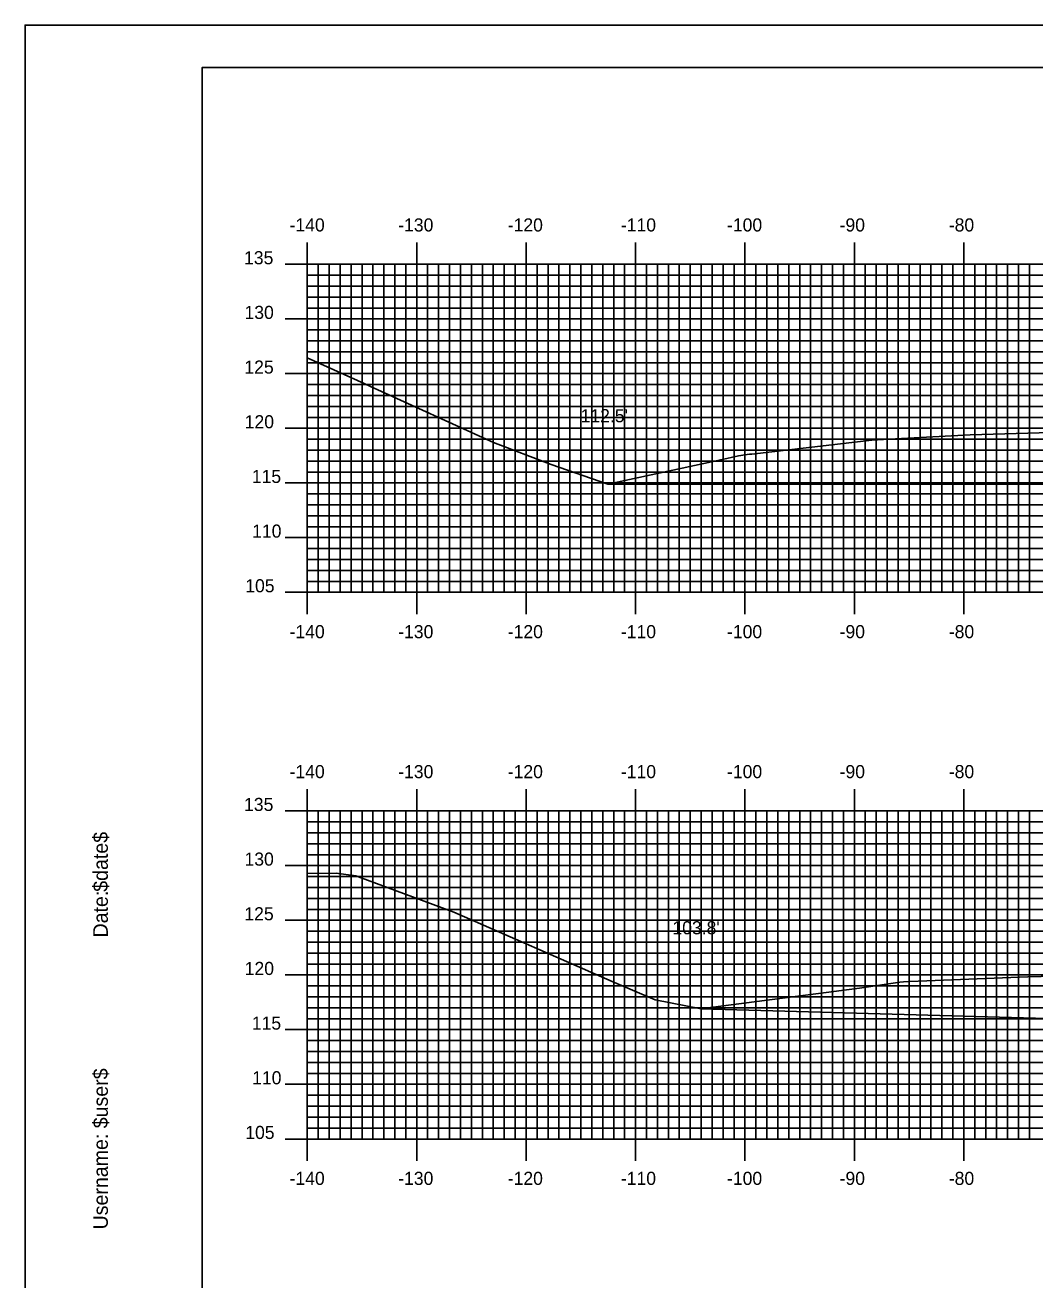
# Model space of a CAD drawing. Extents: x 854681 to 855024, y 366605 to 366825.
# Drawn here: x 854680.8 to 854773.1, y 366710.2 to 366824.9 of the extents above; entities that cross this region are included whole.
import ezdxf

# ---------------------------------------------------------------- set-up
doc = ezdxf.new("R2010")
doc.units = 0
for name, color, linetype in [('ANNOTATION', 7, 'Continuous'), ('BORDER', 7, 'Continuous'), ('D_Text_Standard', 7, 'Continuous'), ('H_V ANNOTATION', 7, 'Continuous'), ('MAJOR', 7, 'Continuous'), ('MINOR', 7, 'Continuous'), ('PLOT BOUNDARY', 7, 'Continuous'), ('S_Roadway_Centerline', 7, 'Continuous')]:
    doc.layers.add(name, color=color, linetype=linetype)

msp = doc.modelspace()

# ---------------------------------------------------------------- linework, layer by layer
at = {"layer": 'ANNOTATION'}
for points in [[(854804.38, 366783.93), (854800.38, 366782.93), (854734.03, 366782.96)], [(854804.38, 366734.36), (854800.38, 366733.36), (854742.57, 366734.98)]]:
    msp.add_lwpolyline(points, dxfattribs=at)
at = {"layer": 'BORDER'}
msp.add_lwpolyline([(854696.96, 366611.06), (855016.96, 366611.06), (855016.96, 366821.06), (854696.96, 366821.06)], close=True, dxfattribs=at)
at = {"layer": 'MAJOR'}
for p, q in [((854706.56, 366805.06), (854706.56, 366803.06)), ((854716.56, 366805.06), (854716.56, 366803.06)), ((854726.56, 366805.06), (854726.56, 366803.06)), ((854736.56, 366805.06), (854736.56, 366803.06)), ((854746.56, 366805.06), (854746.56, 366803.06)), ((854756.56, 366805.06), (854756.56, 366803.06)), ((854766.56, 366805.06), (854766.56, 366803.06)), ((854704.55, 366803.06), (854706.56, 366803.06)), ((854706.56, 366803.06), (854986.56, 366803.06)), ((854706.56, 366773.06), (854706.56, 366803.06)), ((854706.56, 366773.06), (854706.56, 366803.06)), ((854706.56, 366803.06), (854986.56, 366803.06)), ((854716.56, 366773.06), (854716.56, 366803.06)), ((854726.56, 366773.06), (854726.56, 366803.06)), ((854736.56, 366773.06), (854736.56, 366803.06)), ((854746.56, 366773.06), (854746.56, 366803.06)), ((854756.56, 366773.06), (854756.56, 366803.06)), ((854766.56, 366773.06), (854766.56, 366803.06)), ((854704.55, 366798.06), (854706.56, 366798.06)), ((854706.56, 366798.06), (854986.56, 366798.06)), ((854704.55, 366793.06), (854706.56, 366793.06)), ((854706.56, 366793.06), (854986.56, 366793.06)), ((854704.55, 366788.06), (854706.56, 366788.06)), ((854706.56, 366788.06), (854986.56, 366788.06)), ((854704.55, 366783.06), (854706.56, 366783.06)), ((854706.56, 366783.06), (854986.56, 366783.06)), ((854704.55, 366778.06), (854706.56, 366778.06)), ((854706.56, 366778.06), (854986.56, 366778.06)), ((854704.55, 366773.06), (854706.56, 366773.06)), ((854706.56, 366773.06), (854986.56, 366773.06)), ((854706.56, 366773.06), (854986.56, 366773.06)), ((854706.56, 366771.05), (854706.56, 366773.06)), ((854716.56, 366771.05), (854716.56, 366773.06)), ((854726.56, 366771.05), (854726.56, 366773.06)), ((854736.56, 366771.05), (854736.56, 366773.06)), ((854746.56, 366771.05), (854746.56, 366773.06)), ((854756.56, 366771.05), (854756.56, 366773.06)), ((854766.56, 366771.05), (854766.56, 366773.06)), ((854706.56, 366755.06), (854706.56, 366753.06)), ((854716.56, 366755.06), (854716.56, 366753.06)), ((854726.56, 366755.06), (854726.56, 366753.06)), ((854736.56, 366755.06), (854736.56, 366753.06)), ((854746.56, 366755.06), (854746.56, 366753.06)), ((854756.56, 366755.06), (854756.56, 366753.06)), ((854766.56, 366755.06), (854766.56, 366753.06)), ((854704.55, 366753.06), (854706.56, 366753.06)), ((854706.56, 366753.06), (854986.56, 366753.06)), ((854706.56, 366723.06), (854706.56, 366753.06)), ((854706.56, 366723.06), (854706.56, 366753.06)), ((854706.56, 366753.06), (854986.56, 366753.06)), ((854716.56, 366723.06), (854716.56, 366753.06)), ((854726.56, 366723.06), (854726.56, 366753.06)), ((854736.56, 366723.06), (854736.56, 366753.06)), ((854746.56, 366723.06), (854746.56, 366753.06)), ((854756.56, 366723.06), (854756.56, 366753.06)), ((854766.56, 366723.06), (854766.56, 366753.06)), ((854704.55, 366748.06), (854706.56, 366748.06)), ((854706.56, 366748.06), (854986.56, 366748.06)), ((854704.55, 366743.06), (854706.56, 366743.06)), ((854706.56, 366743.06), (854986.56, 366743.06)), ((854704.55, 366738.06), (854706.56, 366738.06)), ((854706.56, 366738.06), (854986.56, 366738.06)), ((854704.55, 366733.06), (854706.56, 366733.06)), ((854706.56, 366733.06), (854986.56, 366733.06)), ((854704.55, 366728.06), (854706.56, 366728.06)), ((854706.56, 366728.06), (854986.56, 366728.06)), ((854704.55, 366723.06), (854706.56, 366723.06)), ((854706.56, 366723.06), (854986.56, 366723.06)), ((854706.56, 366723.06), (854986.56, 366723.06)), ((854706.56, 366721.05), (854706.56, 366723.06)), ((854716.56, 366721.05), (854716.56, 366723.06)), ((854726.56, 366721.05), (854726.56, 366723.06)), ((854736.56, 366721.05), (854736.56, 366723.06)), ((854746.56, 366721.05), (854746.56, 366723.06)), ((854756.56, 366721.05), (854756.56, 366723.06)), ((854766.56, 366721.05), (854766.56, 366723.06))]:
    msp.add_line(p, q, dxfattribs=at)
at = {"layer": 'MINOR'}
for p, q in [((854707.56, 366773.06), (854707.56, 366803.06)), ((854708.56, 366773.06), (854708.56, 366803.06)), ((854709.56, 366773.06), (854709.56, 366803.06)), ((854710.56, 366773.06), (854710.56, 366803.06)), ((854711.56, 366773.06), (854711.56, 366803.06)), ((854712.56, 366773.06), (854712.56, 366803.06)), ((854713.56, 366773.06), (854713.56, 366803.06)), ((854714.56, 366773.06), (854714.56, 366803.06)), ((854715.56, 366773.06), (854715.56, 366803.06)), ((854717.56, 366773.06), (854717.56, 366803.06)), ((854718.56, 366773.06), (854718.56, 366803.06)), ((854719.56, 366773.06), (854719.56, 366803.06)), ((854720.56, 366773.06), (854720.56, 366803.06)), ((854721.56, 366773.06), (854721.56, 366803.06)), ((854722.56, 366773.06), (854722.56, 366803.06)), ((854723.56, 366773.06), (854723.56, 366803.06)), ((854724.56, 366773.06), (854724.56, 366803.06)), ((854725.56, 366773.06), (854725.56, 366803.06)), ((854727.56, 366773.06), (854727.56, 366803.06)), ((854728.56, 366773.06), (854728.56, 366803.06)), ((854729.56, 366773.06), (854729.56, 366803.06)), ((854730.56, 366773.06), (854730.56, 366803.06)), ((854731.56, 366773.06), (854731.56, 366803.06)), ((854732.56, 366773.06), (854732.56, 366803.06)), ((854733.56, 366773.06), (854733.56, 366803.06)), ((854734.56, 366773.06), (854734.56, 366803.06)), ((854735.56, 366773.06), (854735.56, 366803.06)), ((854737.56, 366773.06), (854737.56, 366803.06)), ((854738.56, 366773.06), (854738.56, 366803.06)), ((854739.56, 366773.06), (854739.56, 366803.06)), ((854740.56, 366773.06), (854740.56, 366803.06)), ((854741.56, 366773.06), (854741.56, 366803.06)), ((854742.56, 366773.06), (854742.56, 366803.06)), ((854743.56, 366773.06), (854743.56, 366803.06)), ((854744.56, 366773.06), (854744.56, 366803.06)), ((854745.56, 366773.06), (854745.56, 366803.06)), ((854747.56, 366773.06), (854747.56, 366803.06)), ((854748.56, 366773.06), (854748.56, 366803.06)), ((854749.56, 366773.06), (854749.56, 366803.06)), ((854750.56, 366773.06), (854750.56, 366803.06)), ((854751.56, 366773.06), (854751.56, 366803.06)), ((854752.56, 366773.06), (854752.56, 366803.06)), ((854753.56, 366773.06), (854753.56, 366803.06)), ((854754.56, 366773.06), (854754.56, 366803.06)), ((854755.56, 366773.06), (854755.56, 366803.06)), ((854757.56, 366773.06), (854757.56, 366803.06)), ((854758.56, 366773.06), (854758.56, 366803.06)), ((854759.56, 366773.06), (854759.56, 366803.06)), ((854760.56, 366773.06), (854760.56, 366803.06)), ((854761.56, 366773.06), (854761.56, 366803.06)), ((854762.56, 366773.06), (854762.56, 366803.06)), ((854763.56, 366773.06), (854763.56, 366803.06)), ((854764.56, 366773.06), (854764.56, 366803.06)), ((854765.56, 366773.06), (854765.56, 366803.06)), ((854767.56, 366773.06), (854767.56, 366803.06)), ((854768.56, 366773.06), (854768.56, 366803.06)), ((854769.56, 366773.06), (854769.56, 366803.06)), ((854770.56, 366773.06), (854770.56, 366803.06)), ((854771.56, 366773.06), (854771.56, 366803.06)), ((854772.56, 366773.06), (854772.56, 366803.06)), ((854706.56, 366802.06), (854986.56, 366802.06)), ((854706.56, 366802.06), (854708.56, 366802.06)), ((854706.56, 366801.06), (854986.56, 366801.06)), ((854706.56, 366801.06), (854708.56, 366801.06)), ((854706.56, 366800.06), (854986.56, 366800.06)), ((854706.56, 366800.06), (854708.56, 366800.06)), ((854706.56, 366799.06), (854986.56, 366799.06)), ((854706.56, 366799.06), (854708.56, 366799.06)), ((854706.56, 366797.06), (854986.56, 366797.06)), ((854706.56, 366797.06), (854708.56, 366797.06)), ((854706.56, 366796.06), (854986.56, 366796.06)), ((854706.56, 366796.06), (854708.56, 366796.06)), ((854706.56, 366795.06), (854986.56, 366795.06)), ((854706.56, 366795.06), (854708.56, 366795.06)), ((854706.56, 366794.06), (854986.56, 366794.06)), ((854706.56, 366794.06), (854708.56, 366794.06)), ((854706.56, 366792.06), (854986.56, 366792.06)), ((854706.56, 366792.06), (854708.56, 366792.06)), ((854706.56, 366791.06), (854986.56, 366791.06)), ((854706.56, 366791.06), (854708.56, 366791.06)), ((854706.56, 366790.06), (854986.56, 366790.06)), ((854706.56, 366790.06), (854708.56, 366790.06)), ((854706.56, 366789.06), (854986.56, 366789.06)), ((854706.56, 366789.06), (854708.56, 366789.06)), ((854706.56, 366787.06), (854986.56, 366787.06)), ((854706.56, 366787.06), (854708.56, 366787.06)), ((854706.56, 366786.06), (854986.56, 366786.06)), ((854706.56, 366786.06), (854708.56, 366786.06)), ((854706.56, 366785.06), (854986.56, 366785.06)), ((854706.56, 366785.06), (854708.56, 366785.06)), ((854706.56, 366784.06), (854986.56, 366784.06)), ((854706.56, 366784.06), (854708.56, 366784.06)), ((854706.56, 366782.06), (854986.56, 366782.06)), ((854706.56, 366782.06), (854708.56, 366782.06)), ((854706.56, 366781.06), (854986.56, 366781.06)), ((854706.56, 366781.06), (854708.56, 366781.06)), ((854706.56, 366780.06), (854986.56, 366780.06)), ((854706.56, 366780.06), (854708.56, 366780.06)), ((854706.56, 366779.06), (854986.56, 366779.06)), ((854706.56, 366779.06), (854708.56, 366779.06)), ((854706.56, 366777.06), (854986.56, 366777.06)), ((854706.56, 366777.06), (854708.56, 366777.06)), ((854706.56, 366776.06), (854986.56, 366776.06)), ((854706.56, 366776.06), (854708.56, 366776.06)), ((854706.56, 366775.06), (854986.56, 366775.06)), ((854706.56, 366775.06), (854708.56, 366775.06)), ((854706.56, 366774.06), (854986.56, 366774.06)), ((854706.56, 366774.06), (854708.56, 366774.06)), ((854707.56, 366723.06), (854707.56, 366753.06)), ((854708.56, 366723.06), (854708.56, 366753.06)), ((854709.56, 366723.06), (854709.56, 366753.06)), ((854710.56, 366723.06), (854710.56, 366753.06)), ((854711.56, 366723.06), (854711.56, 366753.06)), ((854712.56, 366723.06), (854712.56, 366753.06)), ((854713.56, 366723.06), (854713.56, 366753.06)), ((854714.56, 366723.06), (854714.56, 366753.06)), ((854715.56, 366723.06), (854715.56, 366753.06)), ((854717.56, 366723.06), (854717.56, 366753.06)), ((854718.56, 366723.06), (854718.56, 366753.06)), ((854719.56, 366723.06), (854719.56, 366753.06)), ((854720.56, 366723.06), (854720.56, 366753.06)), ((854721.56, 366723.06), (854721.56, 366753.06)), ((854722.56, 366723.06), (854722.56, 366753.06)), ((854723.56, 366723.06), (854723.56, 366753.06)), ((854724.56, 366723.06), (854724.56, 366753.06)), ((854725.56, 366723.06), (854725.56, 366753.06)), ((854727.56, 366723.06), (854727.56, 366753.06)), ((854728.56, 366723.06), (854728.56, 366753.06)), ((854729.56, 366723.06), (854729.56, 366753.06)), ((854730.56, 366723.06), (854730.56, 366753.06)), ((854731.56, 366723.06), (854731.56, 366753.06)), ((854732.56, 366723.06), (854732.56, 366753.06)), ((854733.56, 366723.06), (854733.56, 366753.06)), ((854734.56, 366723.06), (854734.56, 366753.06)), ((854735.56, 366723.06), (854735.56, 366753.06)), ((854737.56, 366723.06), (854737.56, 366753.06)), ((854738.56, 366723.06), (854738.56, 366753.06)), ((854739.56, 366723.06), (854739.56, 366753.06)), ((854740.56, 366723.06), (854740.56, 366753.06)), ((854741.56, 366723.06), (854741.56, 366753.06)), ((854742.56, 366723.06), (854742.56, 366753.06)), ((854743.56, 366723.06), (854743.56, 366753.06)), ((854744.56, 366723.06), (854744.56, 366753.06)), ((854745.56, 366723.06), (854745.56, 366753.06)), ((854747.56, 366723.06), (854747.56, 366753.06)), ((854748.56, 366723.06), (854748.56, 366753.06)), ((854749.56, 366723.06), (854749.56, 366753.06)), ((854750.56, 366723.06), (854750.56, 366753.06)), ((854751.56, 366723.06), (854751.56, 366753.06)), ((854752.56, 366723.06), (854752.56, 366753.06)), ((854753.56, 366723.06), (854753.56, 366753.06)), ((854754.56, 366723.06), (854754.56, 366753.06)), ((854755.56, 366723.06), (854755.56, 366753.06)), ((854757.56, 366723.06), (854757.56, 366753.06)), ((854758.56, 366723.06), (854758.56, 366753.06)), ((854759.56, 366723.06), (854759.56, 366753.06)), ((854760.56, 366723.06), (854760.56, 366753.06)), ((854761.56, 366723.06), (854761.56, 366753.06)), ((854762.56, 366723.06), (854762.56, 366753.06)), ((854763.56, 366723.06), (854763.56, 366753.06)), ((854764.56, 366723.06), (854764.56, 366753.06)), ((854765.56, 366723.06), (854765.56, 366753.06)), ((854767.56, 366723.06), (854767.56, 366753.06)), ((854768.56, 366723.06), (854768.56, 366753.06)), ((854769.56, 366723.06), (854769.56, 366753.06)), ((854770.56, 366723.06), (854770.56, 366753.06)), ((854771.56, 366723.06), (854771.56, 366753.06)), ((854772.56, 366723.06), (854772.56, 366753.06)), ((854706.56, 366752.06), (854986.56, 366752.06)), ((854706.56, 366752.06), (854708.56, 366752.06)), ((854706.56, 366751.06), (854986.56, 366751.06)), ((854706.56, 366751.06), (854708.56, 366751.06)), ((854706.56, 366750.06), (854986.56, 366750.06)), ((854706.56, 366750.06), (854708.56, 366750.06)), ((854706.56, 366749.06), (854986.56, 366749.06)), ((854706.56, 366749.06), (854708.56, 366749.06)), ((854706.56, 366747.06), (854986.56, 366747.06)), ((854706.56, 366747.06), (854708.56, 366747.06)), ((854706.56, 366746.06), (854986.56, 366746.06)), ((854706.56, 366746.06), (854708.56, 366746.06)), ((854706.56, 366745.06), (854986.56, 366745.06)), ((854706.56, 366745.06), (854708.56, 366745.06)), ((854706.56, 366744.06), (854986.56, 366744.06)), ((854706.56, 366744.06), (854708.56, 366744.06)), ((854706.56, 366742.06), (854986.56, 366742.06)), ((854706.56, 366742.06), (854708.56, 366742.06)), ((854706.56, 366741.06), (854986.56, 366741.06)), ((854706.56, 366741.06), (854708.56, 366741.06)), ((854706.56, 366740.06), (854986.56, 366740.06)), ((854706.56, 366740.06), (854708.56, 366740.06)), ((854706.56, 366739.06), (854986.56, 366739.06)), ((854706.56, 366739.06), (854708.56, 366739.06)), ((854706.56, 366737.06), (854986.56, 366737.06)), ((854706.56, 366737.06), (854708.56, 366737.06)), ((854706.56, 366736.06), (854986.56, 366736.06)), ((854706.56, 366736.06), (854708.56, 366736.06)), ((854706.56, 366735.06), (854986.56, 366735.06)), ((854706.56, 366735.06), (854708.56, 366735.06)), ((854706.56, 366734.06), (854986.56, 366734.06)), ((854706.56, 366734.06), (854708.56, 366734.06)), ((854706.56, 366732.06), (854986.56, 366732.06)), ((854706.56, 366732.06), (854708.56, 366732.06)), ((854706.56, 366731.06), (854986.56, 366731.06)), ((854706.56, 366731.06), (854708.56, 366731.06)), ((854706.56, 366730.06), (854986.56, 366730.06)), ((854706.56, 366730.06), (854708.56, 366730.06)), ((854706.56, 366729.06), (854986.56, 366729.06)), ((854706.56, 366729.06), (854708.56, 366729.06)), ((854706.56, 366727.06), (854986.56, 366727.06)), ((854706.56, 366727.06), (854708.56, 366727.06)), ((854706.56, 366726.06), (854986.56, 366726.06)), ((854706.56, 366726.06), (854708.56, 366726.06)), ((854706.56, 366725.06), (854986.56, 366725.06)), ((854706.56, 366725.06), (854708.56, 366725.06)), ((854706.56, 366724.06), (854986.56, 366724.06)), ((854706.56, 366724.06), (854708.56, 366724.06))]:
    msp.add_line(p, q, dxfattribs=at)
at = {"layer": 'PLOT BOUNDARY'}
msp.add_lwpolyline([(854680.77, 366604.94), (855020.77, 366604.94), (855020.77, 366824.94), (854680.77, 366824.94)], close=True, dxfattribs=at)
at = {"layer": 'S_Roadway_Centerline'}
for points in [[(854706.56, 366794.51), (854711.75, 366792.16), (854712.34, 366791.89), (854723.59, 366786.75), (854728.85, 366784.75), (854734.03, 366782.96), (854744.34, 366785.19), (854745.96, 366785.53), (854746.96, 366785.69), (854747.2, 366785.7), (854758.14, 366786.99), (854759.73, 366787.08), (854767.13, 366787.45), (854778.72, 366787.8)], [(854706.56, 366747.34), (854709.2, 366747.37), (854710.99, 366747.14), (854719.95, 366743.8), (854734.41, 366737.45), (854738.35, 366735.79), (854742.56, 366734.98), (854742.57, 366734.98), (854742.71, 366735), (854757.03, 366736.85), (854760.7, 366737.4), (854761.06, 366737.44), (854761.62, 366737.46), (854772.42, 366737.9), (854776.1, 366737.98)]]:
    msp.add_lwpolyline(points, dxfattribs=at)

# ---------------------------------------------------------------- texts
at = {"layer": 'BORDER'}
for s, p in [('$date$', (854688.33, 366745.67)), ('Date:', (854688.33, 366741.49)), ('$user$', (854688.33, 366724.04)), ('Username:', (854688.33, 366714.79))]:
    msp.add_text(s, height=1.339, rotation=90, dxfattribs=at).set_placement(p)
at = {"layer": 'D_Text_Standard'}
for s, p in [("112.5'", (854731.54, 366788.61)), ("103.8'", (854739.93, 366741.78))]:
    msp.add_text(s, height=1.2, dxfattribs=at).set_placement(p)
at = {"layer": 'H_V ANNOTATION'}
for s, p in [('-140', (854704.94, 366806.06)), ('-130', (854714.87, 366806.06)), ('-120', (854724.88, 366806.06)), ('-110', (854735.22, 366806.06)), ('-100', (854744.92, 366806.06)), ('-90', (854755.21, 366806.06)), ('-80', (854765.19, 366806.06)), ('135', (854700.78, 366803.06)), ('130', (854700.82, 366798.06)), ('125', (854700.81, 366793.06)), ('120', (854700.84, 366788.06)), ('115', (854701.49, 366783.06)), ('110', (854701.52, 366778.06)), ('105', (854700.89, 366773.06)), ('-140', (854704.94, 366768.86)), ('-130', (854714.87, 366768.86)), ('-120', (854724.88, 366768.86)), ('-110', (854735.22, 366768.86)), ('-100', (854744.92, 366768.86)), ('-90', (854755.21, 366768.86)), ('-80', (854765.19, 366768.86)), ('-140', (854704.94, 366756.06)), ('-130', (854714.87, 366756.06)), ('-120', (854724.88, 366756.06)), ('-110', (854735.22, 366756.06)), ('-100', (854744.92, 366756.06)), ('-90', (854755.21, 366756.06)), ('-80', (854765.19, 366756.06)), ('135', (854700.78, 366753.06)), ('130', (854700.82, 366748.06)), ('125', (854700.81, 366743.06)), ('120', (854700.84, 366738.06)), ('115', (854701.49, 366733.06)), ('110', (854701.52, 366728.06)), ('105', (854700.89, 366723.06)), ('-140', (854704.94, 366718.86)), ('-130', (854714.87, 366718.86)), ('-120', (854724.88, 366718.86)), ('-110', (854735.22, 366718.86)), ('-100', (854744.92, 366718.86)), ('-90', (854755.21, 366718.86)), ('-80', (854765.19, 366718.86))]:
    msp.add_text(s, height=1.2, dxfattribs=at).set_placement(p)
at = {"layer": 'MAJOR'}
for p in [(854706.55, 366773.06), (854706.55, 366723.06)]:
    msp.add_text('-', height=0.012, dxfattribs=at).set_placement(p)

doc.saveas('drawing.dxf')
